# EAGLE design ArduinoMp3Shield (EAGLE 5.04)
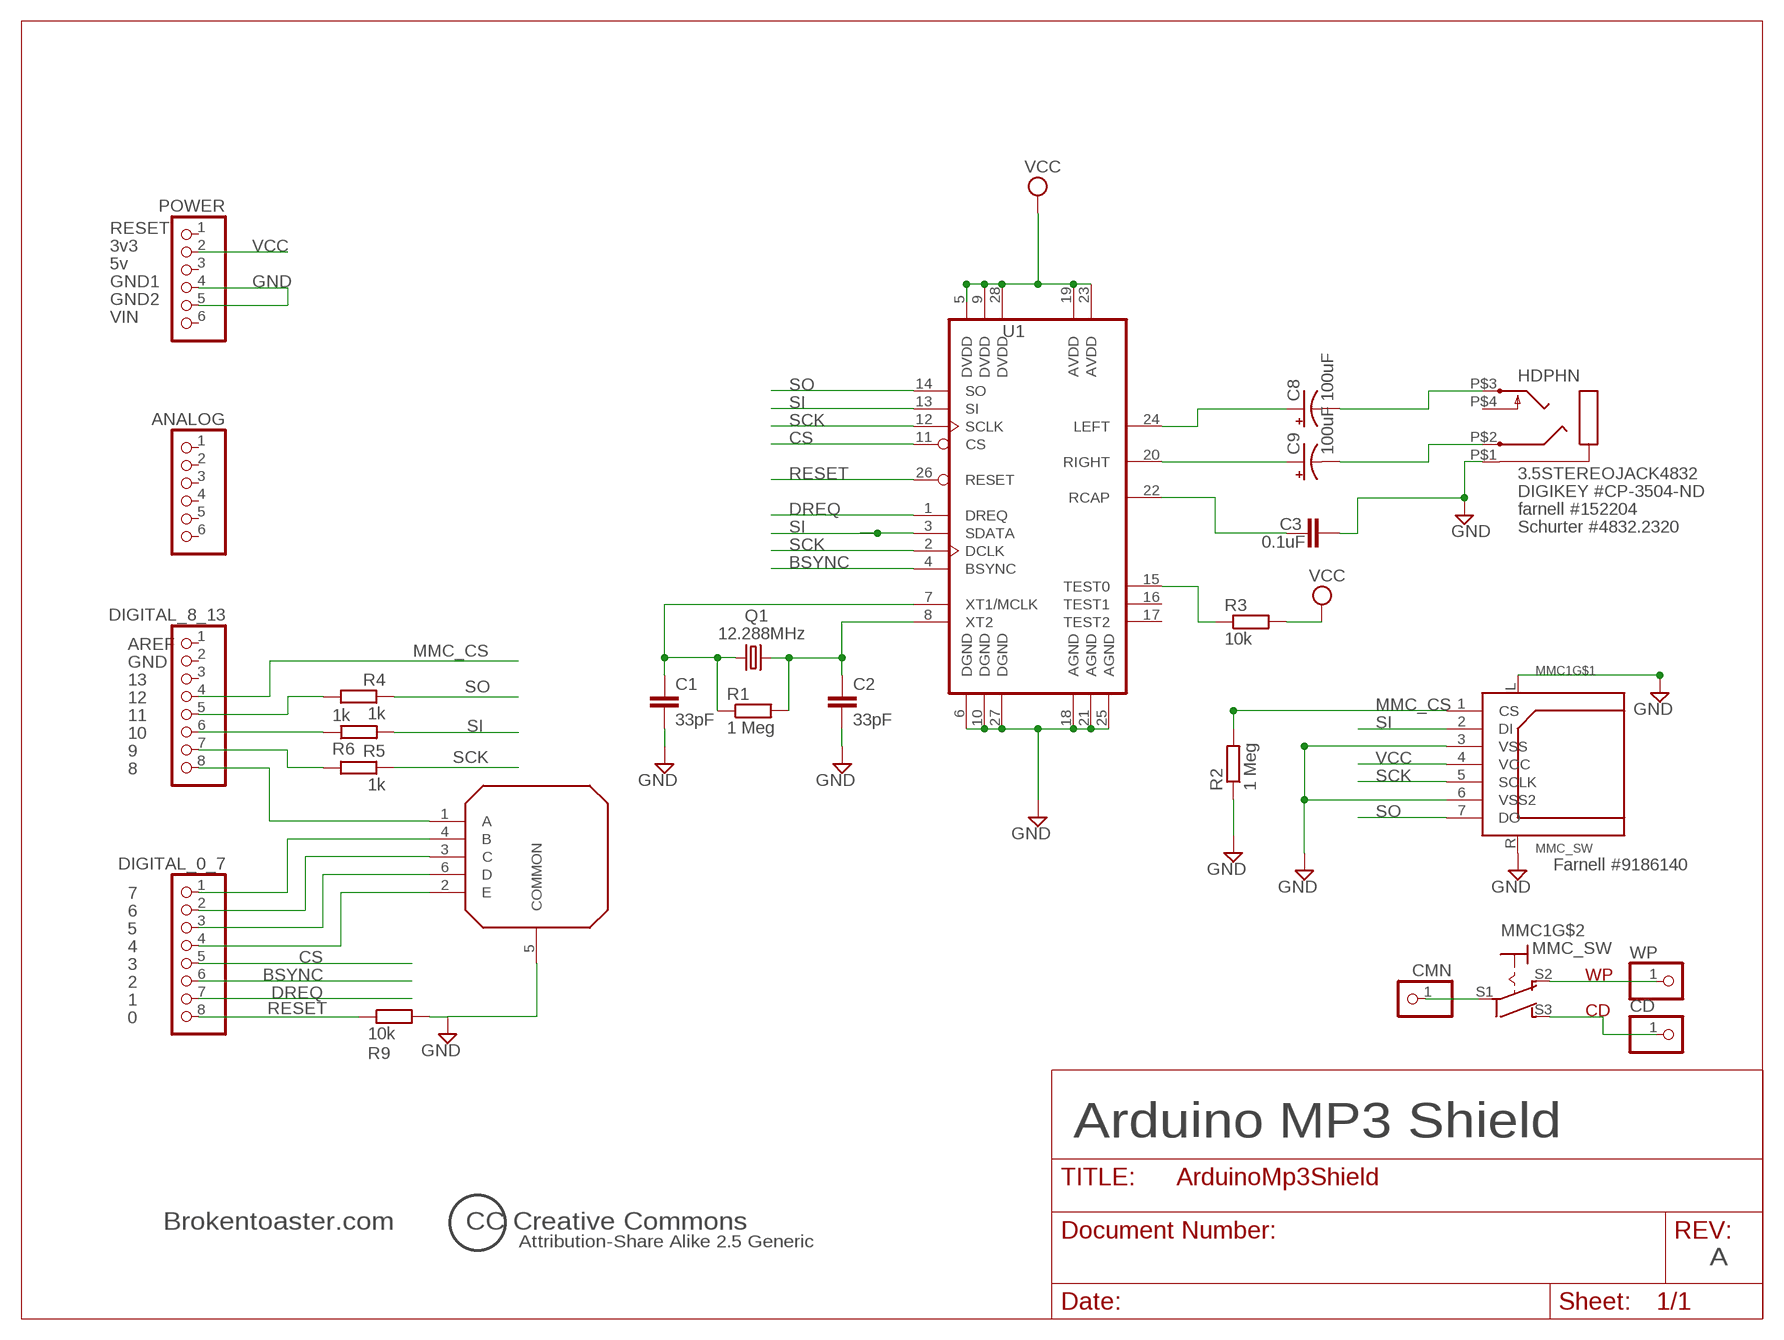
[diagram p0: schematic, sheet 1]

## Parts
ANALOG  1X06  [1X06]
C1  33pF  C-EUC0805K  [C0805K]
C2  33pF  C-EUC0805K  [C0805K]
C3  0.1uF  C-EUC0805K  [C0805K]
C8  100uF  CPOL-USE2.5-6  [E2,5-6]
C9  100uF  CPOL-USE2.5-6  [E2,5-6]
CD  PINHD-1X1  [1X01]
CMN  PINHD-1X1  [1X01]
DIGITAL_0_7  1X08  [1X08]
DIGITAL_8_13  1X08  [1X08]
HDPHN  3.5STEREOJACK4832  [4832-2320]
MMC1  MMC_SW  [SDAMB-01215BT00]
POWER  1X06  [1X06]
Q1  12.288MHz  CRYSTALHC49UP  [HC49UP]
R1  1 Meg  R-EU_R0805  [R0805]
R2  1 Meg  R-EU_R0805  [R0805]
R3  10k  R-EU_R0805  [R0805]
R4  1k  R-EU_R0805  [R0805]
R5  1k  R-EU_R0805  [R0805]
R6  1k  R-EU_R0805  [R0805]
R9  10k  R-EU_R0805  [R0805]
U1  VS1001K  [SOIC-28]
U$5  MCMT5  [MCMT4]
WP  PINHD-1X1  [1X01]

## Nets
BSYNC: DIGITAL_0_7.6 U1.4(BSYNC)
CS: DIGITAL_0_7.5 U1.11(CS)
DREQ: DIGITAL_0_7.7 U1.1(DREQ)
GND: C1.2 C2.2 C3.2 HDPHN.P$1 MMC1.3(VSS) MMC1.6(VSS2) MMC1.L MMC1.R POWER.4 POWER.5 R2.1 R9.2 U1.6(DGND) U1.10(DGND) U1.18(AGND) U1.21(AGND) U1.25(AGND) U1.27(DGND) U$5.5(COMMON)
MMC_CS: DIGITAL_8_13.4 MMC1.1(CS) R2.2
N$1: R3.1 U1.15(TEST0)
N$2: C8.+ U1.24(LEFT)
N$3: C8.- HDPHN.P$3
N$4: C9.+ U1.20(RIGHT)
N$5: C9.- HDPHN.P$2
N$6: DIGITAL_8_13.6 R6.1
N$7: C3.1 U1.22(RCAP)
N$8: DIGITAL_8_13.5 R4.2
N$9: C1.1 Q1.1 R1.1 U1.7(XT1/MCLK)
N$10: C2.1 Q1.2 R1.2 U1.8(XT2)
N$11: DIGITAL_0_7.4 U$5.2(E)
N$12: DIGITAL_0_7.3 U$5.6(D)
N$13: DIGITAL_8_13.7 R5.2
N$14: DIGITAL_0_7.2 U$5.3(C)
N$15: DIGITAL_0_7.1 U$5.4(B)
N$16: DIGITAL_8_13.8 U$5.1(A)
RESET: DIGITAL_0_7.8 R9.1 U1.26(RESET)
SCK: MMC1.5(SCLK) R5.1 U1.2(DCLK) U1.12(SCLK)
SD_SW_CD: CD.1 MMC1.S3(S)
SD_SW_COMM: CMN.1 MMC1.S1(P)
SI: MMC1.2(DI) R6.2 U1.3(SDATA) U1.13(SI)
SO: MMC1.7(DO) R4.1 U1.14(SO)
VCC: MMC1.4(VCC) POWER.2 R3.2 U1.5(DVDD) U1.9(DVDD) U1.19(AVDD) U1.23(AVDD) U1.28(DVDD)
WP: MMC1.S2(O) WP.1
Unconnected: ANALOG.1 ANALOG.2 ANALOG.3 ANALOG.4 ANALOG.5 ANALOG.6 DIGITAL_8_13.1 DIGITAL_8_13.2 DIGITAL_8_13.3 HDPHN.P$4 POWER.1 POWER.3 POWER.6 U1.16(TEST1) U1.17(TEST2)

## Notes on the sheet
- RESET
- 3v3
- 5v
- GND1
- GND2
- VIN
- DIGIKEY #CP-3504-ND
- farnell #152204
- Schurter #4832.2320
- AREF
- GND
- 13
- 12
- 11
- 10
- 9
- 8
- Farnell #9186140
- 7
- 6
- 5
- 4
- 3
- 2
- 1
- 0
- Arduino MP3 Shield
- Brokentoaster.com | CC Creative Commons
- Attribution-Share Alike 2.5 Generic
- A

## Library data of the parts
ANALOG POWER = arduino:1X06: PIN HEADER
C1-C3 = rcl:C-EU: CAPACITOR, European symbol
C8 C9 = ButterflyMP3:CPOL-US: POLARIZED CAPACITOR, American symbol
CD CMN WP = pinhead:PINHD-1X1: PIN HEADER
DIGITAL_0_7 DIGITAL_8_13 = arduino:1X08: PIN HEADER
HDPHN = ButterflyMP3:3.5STEREOJACK: 3.5mm Stero Jack Standard through hole headphone socket. farnell #152204
MMC1 = ButterflyMP3:MMC_SW
Q1 = crystal:CRYSTAL: CRYSTAL
R1-R6 R9 = ButterflyMP3:R-EU_: RESISTOR, European symbol
U1 = ButterflyMP3:VS1001K
U$5 = Switch:MCMT5

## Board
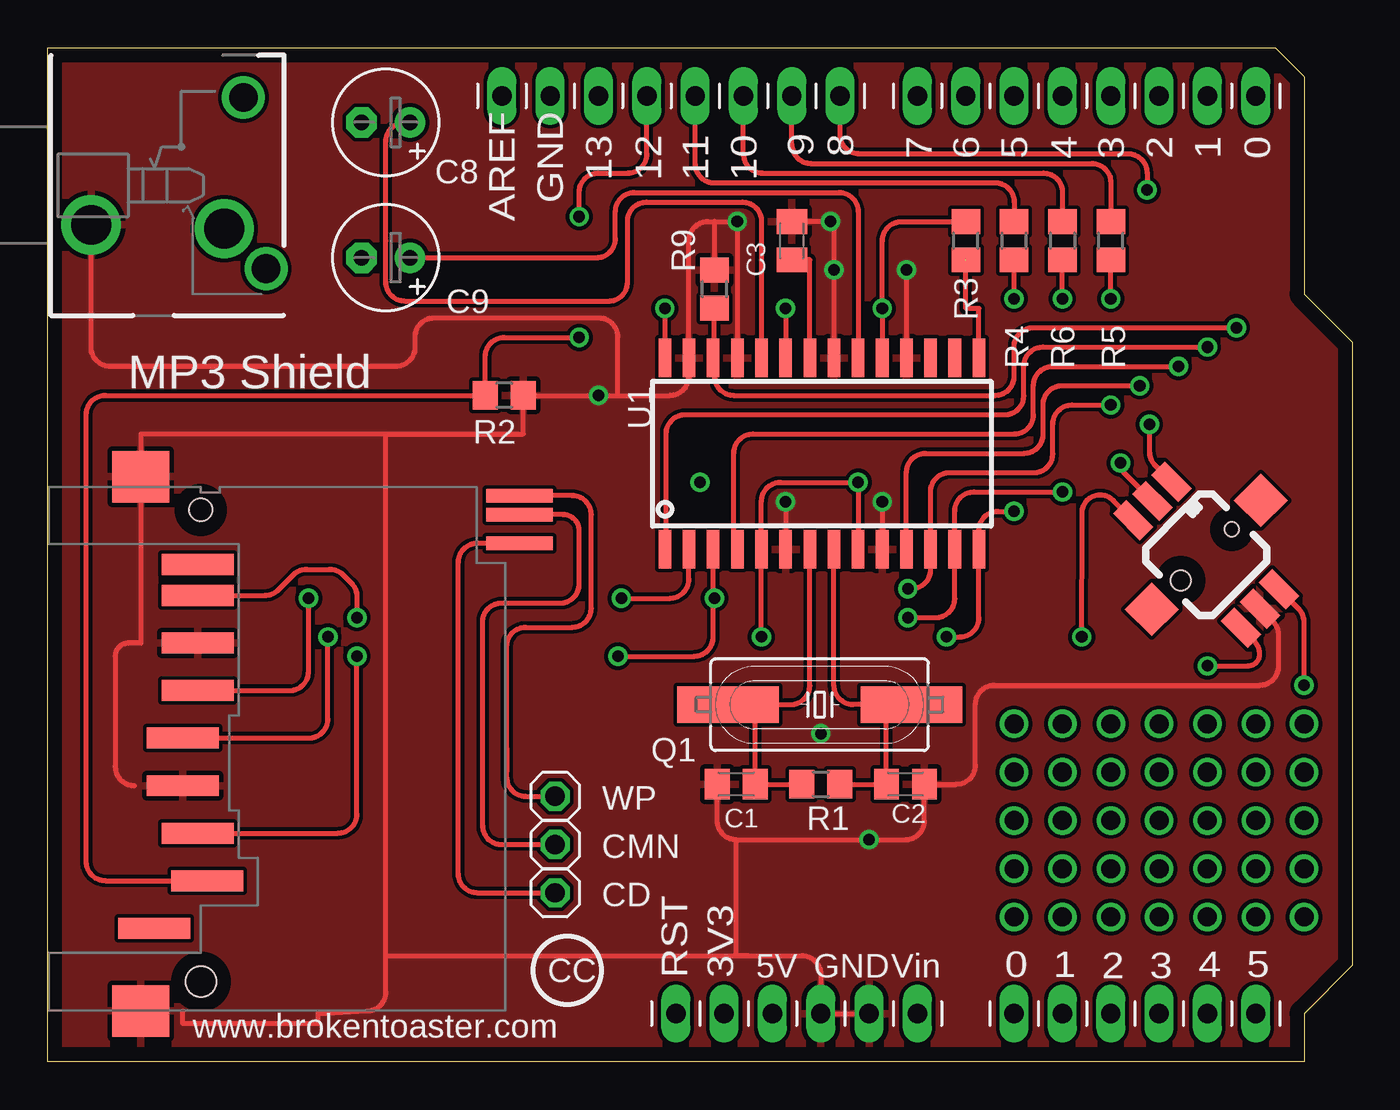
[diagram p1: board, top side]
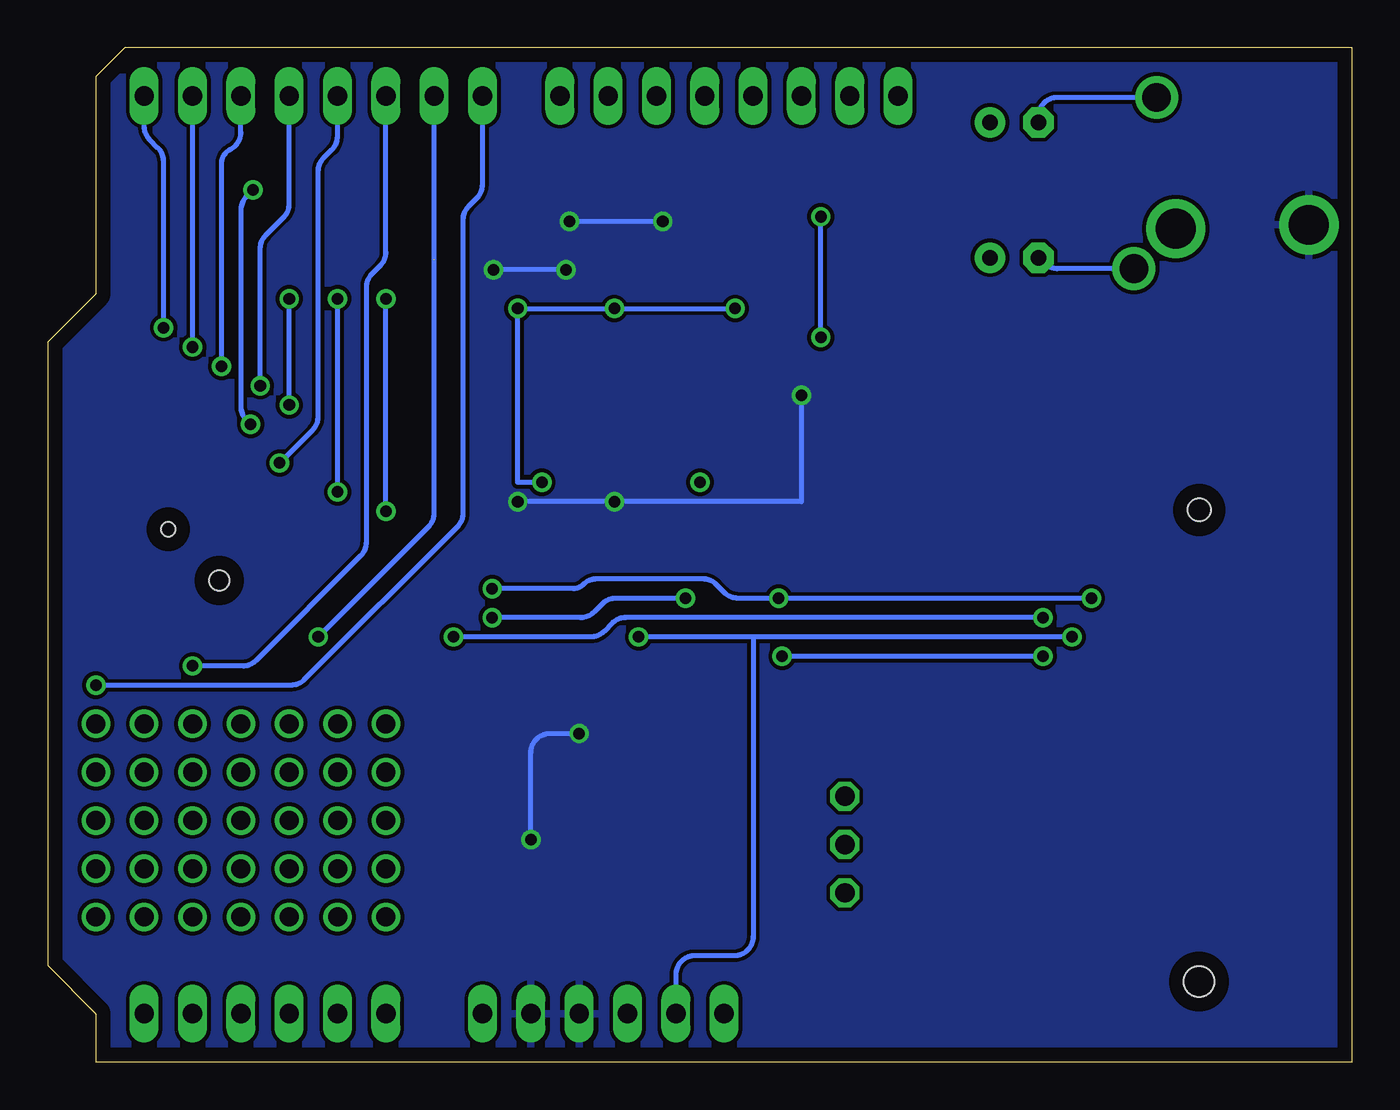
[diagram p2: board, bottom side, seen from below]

Size 68.58 x 53.34 mm. Coordinates in mm from the lower left corner, seen from the top.
Outline: 0,53.34 64.52,53.34 66.04,51.82 66.04,40.39 68.58,37.85 68.58,5.08 66.04,2.54 66.04,0 0,0 0,53.34
Copper layers (1*16): Top 0.035mm / dielectric 1.5mm / Bottom 0.035mm
Design rules "default *": minimum track width 10mil, minimum drill 24mil, track to track 8mil, track to pad 8mil, pad to pad 8mil, via to via 8mil, smd to smd 8mil, copper to edge 30mil, drill to drill 8mil, minimum pad ring 10mil, minimum via ring 8mil, stop-mask expansion 4mil, vias tented up to drill 0mil, thermal gap 10mil

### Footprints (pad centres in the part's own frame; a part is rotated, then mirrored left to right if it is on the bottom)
1X06 = drill 1.016 long: 1 -6.35,0; 2 -3.81,0; 3 -1.27,0; 4 1.27,0; 5 3.81,0; 6 6.35,0
C0805K = smd 1.3 x 1.6: 1 -1,0; 2 1,0
E2,5-6 = drill 0.813 pad 1.6 round: + -1.27,0 | drill 0.813 pad 1.6 octagon: - 1.27,0
1X01 = drill 1.016 octagon: 1 0,0
1X08 = drill 1.016 long: 1 -8.89,0; 2 -6.35,0; 3 -3.81,0; 4 -1.27,0; 5 1.27,0; 6 3.81,0; 7 6.35,0; 8 8.89,0
4832-2320 = drill 2.1 round: P$1 2.5,-2.2; P$4 9.5,-2.4 | drill 1.5 round: P$2 11.7,-4.5; P$3 10.5,4.5
SDAMB-01215BT00 = smd 1.1 x 3.79: 1 -5.3,0.345; 2 -7.8,-0.155; 3 -10.3,-0.955; 4 -12.8,-0.955; 5 -15.3,-0.155; 6 -17.8,-0.155; 7 -20.3,-0.155; 8 -21.925,-0.155; 9 -2.8,-2.455 | smd 2.7 x 3: L -26.55,-3.15; R 1.55,-3.15 | smd 0.7 x 3.5: S1 -24.55,16.75; S2 -25.55,16.75; S3 -23.05,16.75 | hole 1.6: 0,0 | hole 1.2: -24.8,0
HC49UP = smd 5.334 x 1.93: 1 -4.826,0; 2 4.826,0
R0805 = smd 1.3 x 1.5: 1 -1,0; 2 1,0
SOIC-28 = smd 0.66 x 2.032: 1 -6.985,-5.029; 2 -5.715,-5.029; 3 -4.445,-5.029; 4 -3.175,-5.029; 5 -1.905,-5.029; 6 -0.635,-5.029; 7 0.635,-5.029; 8 1.905,-5.029; 9 3.175,-5.029; 10 4.445,-5.029; 11 5.715,-5.029; 12 6.985,-5.029; 13 8.255,-5.029; 14 9.525,-5.029; 15 9.525,5.029; 16 8.255,5.029; 17 6.985,5.029; 18 5.715,5.029; 19 4.445,5.029; 20 3.175,5.029; 21 1.905,5.029; 22 0.635,5.029; 23 -0.635,5.029; 24 -1.905,5.029; 25 -3.175,5.029; 26 -4.445,5.029; 27 -5.715,5.029; 28 -6.985,5.029
MCMT4 = smd 2 x 1: 1 -4,1.425; 2 -4,0; 3 -4,-1.425; 4 4,1.425; 5 4,0; 6 4,-1.425 | smd 2 x 2: NC1 0,4.05; NC2 0,-4.05 | hole 0.75: 0,1.9 | hole 1.05: 0,-1.9

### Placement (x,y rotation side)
ANALOG  57.15,2.54 0 top
C1  36.2,14.61 180 top
C2  45.09,14.61 0 top
C3  39.12,43.18 90 top
C8  17.78,49.4 180 top
C9  17.78,42.29 180 top
CD  26.67,8.89 0 top
CMN  26.67,11.43 0 top
DIGITAL_0_7  54.61,50.8 0 top
DIGITAL_8_13  32.77,50.8 0 top
HDPHN  -0.21,46.22 0 top
MMC1  8.05,4.23 270 top
POWER  39.37,2.54 0 top
Q1  40.58,18.79 0 top
R1  40.64,14.61 0 top
R2  24,35.05 180 top
R3  48.26,43.18 90 top
R4  50.8,43.18 90 top
R5  55.88,43.18 90 top
R6  53.34,43.18 270 top
R9  35.05,40.64 90 top
U1  39.42,31.99 0 top
U$5  60.89,26.67 315 top
WP  26.67,13.97 0 top

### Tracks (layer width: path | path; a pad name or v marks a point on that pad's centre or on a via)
BSYNC  (via drill 0.61)
  Top 0.254: v59.44,36.58 52.82,36.58 arc90 51.82,35.58 51.82,34.02 arc-90 50.82,33.02 37.07,33.02 arc90 36.07,32.02 36.07,26.96 U1.4
  Bottom 0.254: v59.44,36.58 59.44,47.23 arc63 58.97,47.98 arc-63 58.42,48.88 DIGITAL_0_7.6
CS  (via drill 0.61)
  Top 0.254: U1.11 45.14,31 arc-90 46.14,32 51.32,32 arc90 52.32,33 52.32,34.56 arc-90 53.32,35.56 v57.4,35.56
  Bottom 0.254: v57.4,35.56 57.4,42.77 arc45 57.11,43.47 56.17,44.41 arc-45 55.88,45.12 DIGITAL_0_7.5
DREQ  (via drill 0.61)
  Top 0.254: v60.96,37.59 52.31,37.59 arc90 51.31,36.59 51.31,35.04 arc-90 50.31,34.04 33.51,34.04 arc90 32.51,33.04 32.51,26.96 U1.1
  Bottom 0.254: v60.96,37.59 DIGITAL_0_7.7
GND  (via drill 0.61)
  Top 0.254: U1.25 v36.25,44.2 35.05,44.2 | 35.05,44.2 R9.2 | U1.21 v41.33,41.66 41.33,44.2 v41.15,44.2 39.12,44.2 C3.2 | 35.05,44.2 34.71,44.2 arc90 33.71,43.2 U1.27 33.71,36.05 arc-90 32.71,35.05 29.97,35.05 | HDPHN.P$1 2.29,37.58 arc90 3.29,36.58 18.3,36.58 arc90 19.3,37.58 19.3,38.12 arc-90 20.3,39.12 28.97,39.12 arc-90 29.97,38.12 29.97,35.05 | 29.97,35.05 v28.96,35.05 R2.1 25,33.02 17.78,33.02 | 17.78,33.02 4.91,33.02 4.91,22.03 4.25,22.03 arc90 3.56,21.34 3.56,15.53 arc90 4.56,14.53 | 7.11,2.68 7.11,2.03 14.22,2.03 14.22,2.54 16.78,2.68 arc90 17.78,3.68 17.78,5.59 | 17.78,5.59 17.78,33.02 | v45.14,41.66 U1.18 | v43.87,29.46 U1.10 | v38.79,29.46 U1.6 | 36.2,11.68 v43.18,11.68 45.09,11.68 arc90 46.09,12.68 C2.2 47.77,14.61 arc90 48.77,15.61 48.77,18.81 arc-90 49.77,19.81 63.7,19.81 arc90 64.7,20.81 64.7,22.45 arc45 64.41,23.15 U$5.5 | 36.2,11.68 arc-90 35.2,12.68 C1.2 | 17.78,5.59 36.83,5.59 | 36.83,5.59 39.64,5.59 arc-90 40.64,4.59 POWER.4 POWER.5 | 36.2,11.68 36.2,5.59 36.83,5.59
  Bottom 0.254: v36.25,44.2 v41.15,44.2 | v41.33,41.66 v45.14,41.66 | v43.87,29.46 v38.79,29.46 28.96,29.46 v28.96,35.05 | v43.18,11.68 43.18,16.27 arc90 42.18,17.27 v40.64,17.27
  pour Bottom: -2.54,55.88 71.12,55.88 71.12,0 -2.54,0
  pour Top: -5.08,53.34 68.58,53.34 68.58,0 -5.08,0
MMC_CS  (via drill 0.61)
  Top 0.254: v27.94,38.1 24,38.1 arc90 23,37.1 R2.2 3.03,35.05 arc90 2.03,34.05 2.03,10.53 arc90 3.03,9.53 MMC1.1 | v27.94,44.45 27.94,45.74 arc-90 28.94,46.74 30.5,46.74 arc90 31.5,47.74 DIGITAL_8_13.4
  Bottom 0.254: v27.94,38.1 v27.94,44.45
N$1  (1 unrouted)
  Top 0.254: U1.15 48.95,39.62 48.26,39.62 48.26,42.16
N$2
  Top 0.254: U1.24 37.52,44.21 arc90 36.52,45.21 31.48,45.21 arc90 30.48,44.21 30.48,41.91 30.48,41.01 arc-90 29.48,40.01 18.78,40.01 arc-90 17.78,41.01 17.78,43.18 17.78,48.4 arc-90 18.78,49.4 C8.+
N$3
  Bottom 0.254: HDPHN.P$3 15.51,50.72 arc-90 16.51,49.72 C8.-
N$4
  Top 0.254: U1.20 42.6,44.72 arc90 41.6,45.72 30.84,45.72 arc90 29.84,44.72 29.84,43.29 arc-90 28.84,42.29 C9.+
N$5
  Bottom 0.254: HDPHN.P$2 15.52,41.72 arc45 16.23,42.01 C9.-
N$6
  Top 0.254: R6.1 53.34,45.74 arc90 52.34,46.74 37.58,46.74 arc-90 36.58,47.74 DIGITAL_8_13.6
N$7
  Top 0.254: C3.1 40.06,42.18 U1.22
N$8
  Top 0.254: R4.2 50.8,45.23 arc90 49.8,46.23 35.04,46.23 arc-90 34.04,47.23 DIGITAL_8_13.5
N$9
  Top 0.254: U1.7 40.06,19.8 arc-90 39.06,18.8 36.58,18.8 36.58,18.79 | 36.58,18.79 Q1.1 | 36.58,18.79 37.2,18.79 C1.1 R1.1
N$10
  Top 0.254: Q1.2 44.7,18.8 | 44.7,18.8 42.33,18.8 arc-90 41.33,19.8 U1.8 | 44.7,18.8 44.09,18.8 C2.1 R1.2
N$11  (via drill 0.61)
  Top 0.254: U$5.2 56.62,30.95 arc-45 v56.39,31.5
  Bottom 0.254: v56.39,31.5 54.65,33.23 arc-45 54.36,33.94 54.36,46.83 arc45 54.06,47.54 53.63,47.97 arc-45 53.34,48.67 DIGITAL_0_7.4
N$12  (via drill 0.61)
  Top 0.254: U$5.6 63.41,22.14 arc-45 63.7,21.43 arc-90 63.1,20.83 v60.96,20.83
  Bottom 0.254: v60.96,20.83 58.33,20.83 arc-45 57.62,21.12 52.11,26.63 arc-45 51.82,27.34 51.82,40.73 arc45 51.52,41.44 51.09,41.87 arc-45 50.8,42.58 DIGITAL_0_7.3
N$13
  Top 0.254: R5.2 55.88,46.24 arc90 54.88,47.24 40.12,47.24 arc-90 39.12,48.24 DIGITAL_8_13.7
N$14  (via drill 0.61)
  Top 0.254: v54.36,22.35 54.37,28.45 54.37,28.88 arc-90 55.31,29.82 arc-45 56.02,29.53 U$5.3
  Bottom 0.254: v54.36,22.35 48.55,28.16 arc-45 48.26,28.86 DIGITAL_0_7.2
N$15  (via drill 0.61)
  Top 0.254: v66.04,19.81 66.04,23.12 arc45 65.75,23.83 U$5.4
  Bottom 0.254: v66.04,19.81 55.79,19.81 arc-45 55.08,20.11 47.03,28.16 arc-45 46.74,28.86 46.74,44.29 arc45 46.44,45 46.01,45.43 arc-45 45.72,46.13 DIGITAL_0_7.1
N$16  (via drill 0.61)
  Top 0.254: U$5.1 58.2,31.37 arc-45 57.91,32.08 v57.91,33.53 | DIGITAL_8_13.8 41.66,48.75 arc90 42.66,47.75 56.78,47.75 arc-90 57.78,46.75 v57.78,45.85
  Bottom 0.254: v57.91,33.53 58.13,33.74 arc45 58.42,34.45 58.42,44.8 arc45 58.13,45.51 v57.78,45.85
N$17  (via drill 1)
  other vias: 50.8,7.62
N$18  (via drill 1)
  other vias: 66.04,7.62
N$19  (via drill 1)
  other vias: 63.5,7.62
N$20  (via drill 1)
  other vias: 60.96,7.62
N$21  (via drill 1)
  other vias: 58.42,7.62
N$22  (via drill 1)
  other vias: 55.88,7.62
N$23  (via drill 1)
  other vias: 55.88,10.16
N$24  (via drill 1)
  other vias: 58.42,10.16
N$25  (via drill 1)
  other vias: 60.96,10.16
N$26  (via drill 1)
  other vias: 63.5,10.16
N$27  (via drill 1)
  other vias: 66.04,10.16
N$28  (via drill 1)
  other vias: 66.04,12.7
N$29  (via drill 1)
  other vias: 60.96,12.7
N$30  (via drill 1)
  other vias: 63.5,12.7
N$31  (via drill 1)
  other vias: 58.42,12.7
N$32  (via drill 1)
  other vias: 55.88,12.7
N$33  (via drill 1)
  other vias: 53.34,12.7
N$34  (via drill 1)
  other vias: 53.34,10.16
N$35  (via drill 1)
  other vias: 50.8,10.16
N$36  (via drill 1)
  other vias: 50.8,12.7
N$37  (via drill 1)
  other vias: 50.8,15.24
N$38  (via drill 1)
  other vias: 53.34,15.24
N$39  (via drill 1)
  other vias: 55.88,15.24
N$40  (via drill 1)
  other vias: 58.42,15.24
N$41  (via drill 1)
  other vias: 60.96,15.24
N$42  (via drill 1)
  other vias: 63.5,15.24
N$43  (via drill 1)
  other vias: 66.04,15.24
N$44  (via drill 1)
  other vias: 66.04,17.78
N$45  (via drill 1)
  other vias: 63.5,17.78
N$46  (via drill 1)
  other vias: 60.96,17.78
N$47  (via drill 1)
  other vias: 58.42,17.78
N$48  (via drill 1)
  other vias: 55.88,17.78
N$49  (via drill 1)
  other vias: 53.34,17.78
N$50  (via drill 1)
  other vias: 50.8,17.78
N$51  (via drill 0.61)
  other vias: 34.29,30.48
N$52  (via drill 1)
  other vias: 53.34,7.62
RESET  (via drill 0.61)
  Top 0.254: v62.48,38.61 51.8,38.61 arc90 50.8,37.61 50.8,36.05 arc-90 49.8,35.05 36.05,35.05 arc-90 35.05,36.05 35.05,36.07 | 35.05,36.07 35.05,37.02 U1.26 | 35.05,36.07 R9.1
  Bottom 0.254: v62.48,38.61 62.48,47.35 arc-45 62.78,48.06 63.21,48.49 arc45 63.5,49.2 DIGITAL_0_7.8
SCK  (via drill 0.61)
  Top 0.254: v55.88,40.13 R5.1 | v55.88,34.54 53.83,34.54 arc90 52.83,33.54 52.83,31.99 arc-90 51.83,30.99 47.41,30.99 arc90 46.41,29.99 U1.12 46.41,25.89 arc-90 45.41,24.89 v45.21,24.89 | v13.72,24.38 13.72,20.53 arc-90 12.72,19.53 MMC1.5 | v30.15,24.38 32.71,24.38 arc90 33.71,25.38 U1.2
  Bottom 0.254: v55.88,34.54 v55.88,40.13 | v13.72,24.38 v30.15,24.38 32.3,24.38 arc45 33,24.68 33.43,25.11 arc-45 34.14,25.4 39.72,25.4 arc-45 40.42,25.11 arc45 40.94,24.89 v45.21,24.89
SD_SW_CD
  Top 0.254: MMC1.S3 22.59,27.28 arc90 21.59,26.28 21.59,9.89 arc90 22.59,8.89 CD.1
SD_SW_COMM
  Top 0.254: CMN.1 23.86,11.43 arc-90 22.86,12.43 22.86,23.13 arc-90 23.86,24.13 26.94,24.13 arc90 27.94,25.13 27.94,27.94 arc90 27.1,28.78 MMC1.S1
SI  (via drill 0.61)
  Top 0.254: v53.34,40.13 R6.2 | v53.34,29.97 48.68,29.97 arc90 47.68,28.97 U1.13 47.68,24.37 arc-90 46.68,23.37 v45.21,23.37 | v16.26,21.34 16.26,13.03 arc-90 15.26,12.03 MMC1.2 | 34.98,24.38 U1.3 | v29.97,21.34 33.98,21.34 arc90 34.98,22.34 34.98,24.38 | 34.98,24.38 v35.05,24.38
  Bottom 0.254: v53.34,29.97 v53.34,40.13 | v16.26,21.34 v29.97,21.34 | v35.05,24.38 38.72,24.38 arc-45 39.42,24.09 39.85,23.66 arc45 40.56,23.37 v45.21,23.37
SO  (via drill 0.61)
  Top 0.254: v50.8,40.13 R4.1 | v50.8,28.96 49.95,28.96 arc90 48.95,27.96 U1.14 48.95,23.35 arc-90 47.95,22.35 v47.24,22.35 | v16.26,23.37 16.26,24.48 arc45 15.96,25.18 15.53,25.61 arc45 14.83,25.91 13.62,25.91 arc45 12.91,25.61 12.12,24.82 arc-45 11.42,24.53 MMC1.7
  Bottom 0.254: v50.8,28.96 v50.8,40.13 | v47.24,22.35 40.04,22.35 arc-45 39.33,22.64 38.9,23.07 arc45 38.19,23.37 v16.26,23.37
VCC  (via drill 0.61)
  Top 0.254: v14.73,22.35 14.73,18.03 arc-90 13.73,17.03 MMC1.4 | v37.52,22.35 U1.5 37.52,29.48 arc-90 38.52,30.48 v42.6,30.48 U1.9 | U1.19 v43.87,39.62 43.87,43.18 arc-90 44.87,44.18 R3.2 | v32.44,39.62 U1.28 | v38.79,39.62 U1.23
  Bottom 0.254: v14.73,22.35 31.5,22.35 | 31.5,22.35 31.5,6.59 arc90 32.5,5.59 34.56,5.59 arc-90 35.56,4.59 POWER.2 | 31.5,22.35 v37.52,22.35 | v32.44,39.62 v38.79,39.62 v43.87,39.62 43.87,30.48 v42.6,30.48
WP
  Top 0.254: MMC1.S2 27.57,29.78 arc-90 28.57,28.78 28.57,23.86 arc-90 27.57,22.86 25.13,22.86 arc90 24.13,21.86 24.13,16.51 | 24.13,16.51 24.13,15.24 | WP.1 25.13,13.97 arc-90 24.13,14.97 24.13,16.51

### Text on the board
tPlace: MP3 Shield | CC | www.brokentoaster.com
tNames: 9 | 8 | 7 | 6 | 5 | 4 | 3 | 2 | 1 | 0 | 13 | 12 | 11 | 10 | GND | AREF | RST | 3V3 | 5V | GND | Vin | 0 | 1 | 2 | 3 | 4 | 5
